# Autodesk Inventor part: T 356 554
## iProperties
Company: Mayer & Müller AG Schaltgeräte
Created: 2005-10
Part Number: T 356 554
Material: 1.4301
Document SubType Name: Modeling
Designer: I.Baliuc
Manufacturer: Standard
Standards Organization: Custom
Description: Bolzen
Density: 7.86 g/cm^3
HalbzeugNorm: DIN 176
Zweck: Trenner Schaltrohr
Abmessung: VA Rd 20
Author: T.Messerschmitt
Revision Number: 356554
Keywords: 380049
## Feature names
1. Extrusion2
2. Extrusion4
3. Fase2 [Chamfer]
4. Extrusion3
5. Extrusion5
6. Extrusion6
7. Fase3 [Chamfer]
